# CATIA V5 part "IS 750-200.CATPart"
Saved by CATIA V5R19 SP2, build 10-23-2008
Part number: IS 750-200
Bounding box of the stored display mesh (mm): x -24.865 to 24.865, y -24.997 to 24.997, z 0 to 495
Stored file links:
  C:\Users\Bora\Desktop\3D Katı model\IS serisi\IS 750\IS 750-200.CATPart
  C:\Program Files\Dassault Systemes\B19\intel_a\reffiles\standard\MetricThickPitch.txt
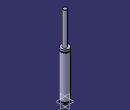
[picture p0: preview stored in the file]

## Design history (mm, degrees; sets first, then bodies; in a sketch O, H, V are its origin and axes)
Body1 (main body)
  Sketch1 on yz-plane, origin (0, 0, 0), H (0, 1, 0), V (0, 0, 1)
    point P1 (25, 279.5)
    point P4 (25, 275.5)
    point P7 (12.5, 494)
    point P9 (12.5, 494)
    point P13 (25, 279.5)
    point P14 (25, 275.5)
    line L1 (25, 279.5) -> (25, 292)
    line L2 (25, 13) -> (25, 275.5)
    line L3 (21.5, 13) -> (21.5, 8)
    arc A1 centre (11.5, 494) radius 1 from (12.5, 494) to (11.5, 495) ccw
    line L4 (12.5, 494) -> (12.5, 292)
    line L5 (25, 0) -> (25, 8)
    arc A2 centre (25, 277.5) radius 2 from (25, 279.5) to (25, 275.5) ccw
    line L6 (11.5, 495) -> (0, 495)
    point P15 (0, 495)
    line L7 (12.5, 292) -> (25, 292)
    line L8 (0, 0) -> (25, 0)
    line L9 (21.5, 8) -> (25, 8)
    line L10 (21.5, 13) -> (25, 13)
    coincidence: P15 V, P1 P13, P4 P14, P7 P9
    tangency: L6 A1
    horizontal: L7 H, L8 H, L9 H, L10 H
  Shaft1: profile Sketch1, axis Sketch1.V, angle 360
  Sketch2 on face of Shaft1 from Sketch1.L8, origin (0, 0, 0), H (1, 0, 0), V (0, -1, 0)
    point P1 (10, 0)
    distance P1 V = 10
  Hole1: placed by Sketch2, at (10, 0, 0) direction (0, 0, 1), diameter 6.647, depth 13, threaded "M8", thread diameter 8, thread depth 13, pitch 1.25
  Sketch3 on face of Shaft1 from Sketch1.L8, origin (0, 0, 0), H (1, 0, 0), V (0, -1, 0)
    point P1 (-10, 0)
    distance P1 V = 10
  Hole2: placed by Sketch3, at (-10, 0, 0) direction (0, 0, 1), diameter 6.647, depth 13, threaded "M8", thread diameter 8, thread depth 13, pitch 1.25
